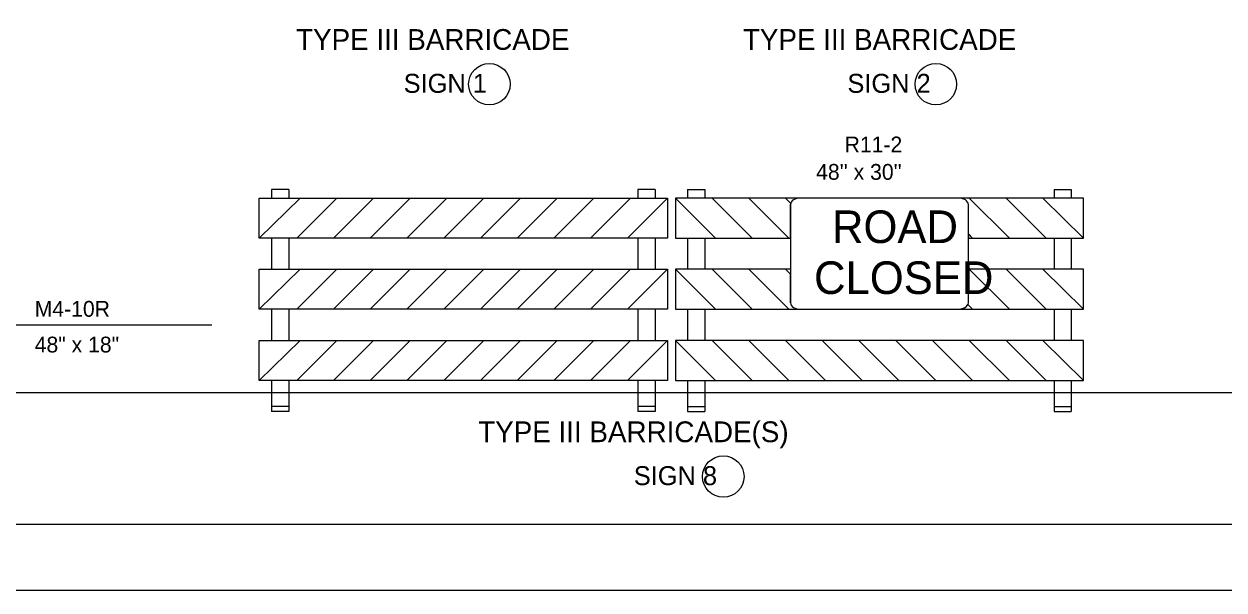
# Model space of a CAD drawing. Extents: x 1615234 to 1620694, y 898143 to 902846.
# Drawn here: x 1616745 to 1618110, y 899546 to 900191 of the extents above; entities that cross this region are included whole.
import ezdxf

# ---------------------------------------------------------------- set-up
doc = ezdxf.new("R2010")
doc.units = 0
for name, color, linetype in [('DEV BORDER CELL', 7, 'Continuous'), ('DEV TYPE 3 BARRICADE DOUBLE WITH R11-2 CELL', 7, 'Continuous'), ('DEV TYPE 3 BARRICADE WITH R11-2 M4-10R CELL', 7, 'Continuous'), ('DEV TYPE 3 BARRICADE WITH R11-3 M4-10L CELL', 7, 'Continuous'), ('DEV TYPE 3 BARRICADE WITH R11-4 M4-10R CELL', 7, 'Continuous'), ('Old_Level_28', 7, 'Continuous'), ('Scratch_Level_0', 7, 'Continuous'), ('Sheet Plot Border Outside CELL', 7, 'Continuous')]:
    doc.layers.add(name, color=color, linetype=linetype)

msp = doc.modelspace()

# ---------------------------------------------------------------- linework, layer by layer
at = {"layer": 'DEV BORDER CELL'}
msp.add_lwpolyline([(1620223.1, 902771.2), (1615723.1, 902771.2), (1615723.1, 899621.2), (1620223.1, 899621.2)], close=True, dxfattribs=at)
at = {"layer": 'DEV TYPE 3 BARRICADE DOUBLE WITH R11-2 CELL'}
for p, q in [((1617045.7, 900002.2), (1617026, 900002.2)), ((1617026, 900002.2), (1617026, 899992.4)), ((1617045.7, 900002.2), (1617045.7, 899992.4)), ((1617462.6, 900002.2), (1617442.9, 900002.2)), ((1617442.9, 900002.2), (1617442.9, 899992.4)), ((1617462.6, 900002.2), (1617462.6, 899992.4)), ((1617499.3, 900002.2), (1617519, 900002.2)), ((1617499.3, 900002.2), (1617499.3, 899992.4)), ((1617519, 900002.2), (1617519, 899992.4)), ((1617916.2, 900002.2), (1617935.9, 900002.2)), ((1617916.2, 900002.2), (1617916.2, 899992.4)), ((1617935.9, 900002.2), (1617935.9, 899992.4)), ((1617012.2, 899992.4), (1617476.4, 899992.4)), ((1617012.2, 899946.8), (1617012.2, 899992.4)), ((1617012.2, 899946.8), (1617012.2, 899992.4)), ((1617012.2, 899992.4), (1617058.5, 899992.4)), ((1617058.5, 899992.4), (1617012.2, 899946.8)), ((1617054.7, 899946.8), (1617100.3, 899992.4)), ((1617142, 899992.4), (1617096.5, 899946.8)), ((1617100.3, 899992.4), (1617142, 899992.4)), ((1617138.3, 899946.8), (1617183.8, 899992.4)), ((1617225.6, 899992.4), (1617180.1, 899946.8)), ((1617183.8, 899992.4), (1617225.6, 899992.4)), ((1617222, 899946.8), (1617267.5, 899992.4)), ((1617309.3, 899992.4), (1617263.8, 899946.8)), ((1617267.5, 899992.4), (1617309.3, 899992.4)), ((1617305.6, 899946.8), (1617351.1, 899992.4)), ((1617392.9, 899992.4), (1617347.3, 899946.8)), ((1617351.1, 899992.4), (1617392.9, 899992.4)), ((1617389.1, 899946.8), (1617434.6, 899992.4)), ((1617476.4, 899992.4), (1617430.9, 899946.8)), ((1617434.6, 899992.4), (1617476.4, 899992.4)), ((1617476.4, 899992.4), (1617476.4, 899946.8)), ((1617949.7, 899992.4), (1617485.5, 899992.4)), ((1617485.5, 899992.4), (1617485.5, 899946.8)), ((1617527.2, 899992.4), (1617485.5, 899992.4)), ((1617485.5, 899992.4), (1617531, 899946.8)), ((1617572.8, 899946.8), (1617527.2, 899992.4)), ((1617610.8, 899992.4), (1617569, 899992.4)), ((1617569, 899992.4), (1617614.5, 899946.8)), ((1617616.6, 899986.5), (1617610.8, 899992.4)), ((1617861.6, 899992.4), (1617819.8, 899992.4)), ((1617819.8, 899992.4), (1617865.4, 899946.8)), ((1617907.1, 899946.8), (1617861.6, 899992.4)), ((1617949.7, 899992.4), (1617903.4, 899992.4)), ((1617903.4, 899992.4), (1617949.7, 899946.8)), ((1617949.7, 899946.8), (1617949.7, 899992.4)), ((1617949.7, 899946.8), (1617949.7, 899992.4)), ((1617616.4, 899946.8), (1617616.4, 899985)), ((1617476.4, 899946.8), (1617012.2, 899946.8)), ((1617026, 899946.8), (1617026, 899911.4)), ((1617045.7, 899946.8), (1617045.7, 899911.4)), ((1617096.5, 899946.8), (1617054.7, 899946.8)), ((1617180.1, 899946.8), (1617138.3, 899946.8)), ((1617263.8, 899946.8), (1617222, 899946.8)), ((1617347.3, 899946.8), (1617305.6, 899946.8)), ((1617430.9, 899946.8), (1617389.1, 899946.8)), ((1617442.9, 899946.8), (1617442.9, 899911.4)), ((1617462.6, 899946.8), (1617462.6, 899911.4)), ((1617485.5, 899946.8), (1617616.4, 899946.8)), ((1617499.3, 899946.8), (1617499.3, 899911.4)), ((1617519, 899946.8), (1617519, 899911.4)), ((1617531, 899946.8), (1617572.8, 899946.8)), ((1617614.5, 899946.8), (1617616.4, 899946.8)), ((1617823.6, 899946.8), (1617818.8, 899951.7)), ((1617818.8, 899951.7), (1617818.8, 899946.8)), ((1617818.8, 899946.8), (1617823.6, 899946.8)), ((1617818.8, 899946.8), (1617949.7, 899946.8)), ((1617865.4, 899946.8), (1617907.1, 899946.8)), ((1617916.2, 899946.8), (1617916.2, 899911.4)), ((1617935.9, 899946.8), (1617935.9, 899911.4)), ((1617012.2, 899911.4), (1617476.4, 899911.4)), ((1617012.2, 899865.9), (1617012.2, 899911.4)), ((1617012.2, 899865.9), (1617012.2, 899911.4)), ((1617012.2, 899911.4), (1617058.5, 899911.4)), ((1617058.5, 899911.4), (1617012.2, 899865.9)), ((1617054.7, 899865.9), (1617100.3, 899911.4)), ((1617142, 899911.4), (1617096.5, 899865.9)), ((1617100.3, 899911.4), (1617142, 899911.4)), ((1617138.3, 899865.9), (1617183.8, 899911.4)), ((1617225.6, 899911.4), (1617180.1, 899865.9)), ((1617183.8, 899911.4), (1617225.6, 899911.4)), ((1617222, 899865.9), (1617267.5, 899911.4)), ((1617309.3, 899911.4), (1617263.8, 899865.9)), ((1617267.5, 899911.4), (1617309.3, 899911.4)), ((1617305.6, 899865.9), (1617351.1, 899911.4)), ((1617392.9, 899911.4), (1617347.3, 899865.9)), ((1617351.1, 899911.4), (1617392.9, 899911.4)), ((1617389.1, 899865.9), (1617434.6, 899911.4)), ((1617476.4, 899911.4), (1617430.9, 899865.9)), ((1617434.6, 899911.4), (1617476.4, 899911.4)), ((1617476.4, 899911.4), (1617476.4, 899865.9)), ((1617485.5, 899911.4), (1617485.5, 899865.9)), ((1617527.2, 899911.4), (1617485.5, 899911.4)), ((1617485.5, 899911.4), (1617531, 899865.9)), ((1617616.4, 899911.4), (1617485.5, 899911.4)), ((1617572.8, 899865.9), (1617527.2, 899911.4)), ((1617569, 899911.4), (1617614.5, 899865.9)), ((1617610.8, 899911.4), (1617569, 899911.4)), ((1617616.4, 899905.8), (1617610.8, 899911.4)), ((1617616.4, 899873.2), (1617616.4, 899905.8)), ((1617949.7, 899911.4), (1617818.8, 899911.4)), ((1617861.6, 899911.4), (1617819.8, 899911.4)), ((1617819.8, 899911.4), (1617865.4, 899865.9)), ((1617907.1, 899865.9), (1617861.6, 899911.4)), ((1617949.7, 899911.4), (1617903.4, 899911.4)), ((1617903.4, 899911.4), (1617949.7, 899865.9)), ((1617949.7, 899865.9), (1617949.7, 899911.4)), ((1617949.7, 899865.9), (1617949.7, 899911.4)), ((1617476.4, 899865.9), (1617012.2, 899865.9)), ((1617026, 899865.9), (1617026, 899830.4)), ((1617045.7, 899865.9), (1617045.7, 899830.4)), ((1617096.5, 899865.9), (1617054.7, 899865.9)), ((1617180.1, 899865.9), (1617138.3, 899865.9)), ((1617263.8, 899865.9), (1617222, 899865.9)), ((1617347.3, 899865.9), (1617305.6, 899865.9)), ((1617430.9, 899865.9), (1617389.1, 899865.9)), ((1617442.9, 899865.9), (1617442.9, 899830.4)), ((1617462.6, 899865.9), (1617462.6, 899830.4)), ((1617485.5, 899865.9), (1617949.7, 899865.9)), ((1617499.3, 899865.9), (1617499.3, 899830.4)), ((1617519, 899865.9), (1617519, 899830.4)), ((1617531, 899865.9), (1617572.8, 899865.9)), ((1617614.5, 899865.9), (1617628.1, 899865.9)), ((1617628.2, 899865.9), (1617807, 899865.9)), ((1617807, 899865.9), (1617823.6, 899865.9)), ((1617823.6, 899865.9), (1617818.3, 899871.2)), ((1617865.4, 899865.9), (1617907.1, 899865.9)), ((1617916.2, 899865.9), (1617916.2, 899830.4)), ((1617935.9, 899865.9), (1617935.9, 899830.4)), ((1617012.2, 899784.9), (1617012.2, 899830.4)), ((1617012.2, 899830.4), (1617058.5, 899830.4)), ((1617058.5, 899830.4), (1617012.2, 899784.9)), ((1617012.2, 899830.4), (1617476.4, 899830.4)), ((1617012.2, 899784.9), (1617012.2, 899830.4)), ((1617054.7, 899784.9), (1617100.3, 899830.4)), ((1617142, 899830.4), (1617096.5, 899784.9)), ((1617100.3, 899830.4), (1617142, 899830.4)), ((1617138.3, 899784.9), (1617183.8, 899830.4)), ((1617225.6, 899830.4), (1617180.1, 899784.9)), ((1617183.8, 899830.4), (1617225.6, 899830.4)), ((1617222, 899784.9), (1617267.5, 899830.4)), ((1617309.3, 899830.4), (1617263.8, 899784.9)), ((1617267.5, 899830.4), (1617309.3, 899830.4)), ((1617305.6, 899784.9), (1617351.1, 899830.4)), ((1617392.9, 899830.4), (1617347.3, 899784.9)), ((1617351.1, 899830.4), (1617392.9, 899830.4)), ((1617389.1, 899784.9), (1617434.6, 899830.4)), ((1617476.4, 899830.4), (1617430.9, 899784.9)), ((1617434.6, 899830.4), (1617476.4, 899830.4)), ((1617476.4, 899830.4), (1617476.4, 899784.9)), ((1617527.2, 899830.4), (1617485.5, 899830.4)), ((1617485.5, 899830.4), (1617531, 899784.9)), ((1617949.7, 899830.4), (1617485.5, 899830.4)), ((1617485.5, 899830.4), (1617485.5, 899784.9)), ((1617572.8, 899784.9), (1617527.2, 899830.4)), ((1617610.8, 899830.4), (1617569, 899830.4)), ((1617569, 899830.4), (1617614.5, 899784.9)), ((1617656.3, 899784.9), (1617610.8, 899830.4)), ((1617694.3, 899830.4), (1617652.6, 899830.4)), ((1617652.6, 899830.4), (1617698.1, 899784.9)), ((1617739.8, 899784.9), (1617694.3, 899830.4)), ((1617778.1, 899830.4), (1617736.3, 899830.4)), ((1617736.3, 899830.4), (1617781.8, 899784.9)), ((1617823.6, 899784.9), (1617778.1, 899830.4)), ((1617861.6, 899830.4), (1617819.8, 899830.4)), ((1617819.8, 899830.4), (1617865.4, 899784.9)), ((1617907.1, 899784.9), (1617861.6, 899830.4)), ((1617949.7, 899830.4), (1617903.4, 899830.4)), ((1617903.4, 899830.4), (1617949.7, 899784.9)), ((1617949.7, 899784.9), (1617949.7, 899830.4)), ((1617949.7, 899784.9), (1617949.7, 899830.4)), ((1617476.4, 899784.9), (1617012.2, 899784.9)), ((1617026, 899784.9), (1617026, 899749.4)), ((1617045.7, 899784.9), (1617045.7, 899749.4)), ((1617096.5, 899784.9), (1617054.7, 899784.9)), ((1617180.1, 899784.9), (1617138.3, 899784.9)), ((1617263.8, 899784.9), (1617222, 899784.9)), ((1617347.3, 899784.9), (1617305.6, 899784.9)), ((1617430.9, 899784.9), (1617389.1, 899784.9)), ((1617442.9, 899784.9), (1617442.9, 899749.4)), ((1617462.6, 899784.9), (1617462.6, 899749.4)), ((1617485.5, 899784.9), (1617949.7, 899784.9)), ((1617499.3, 899784.9), (1617499.3, 899749.4)), ((1617519, 899784.9), (1617519, 899749.4)), ((1617531, 899784.9), (1617572.8, 899784.9)), ((1617614.5, 899784.9), (1617656.3, 899784.9)), ((1617698.1, 899784.9), (1617739.8, 899784.9)), ((1617781.8, 899784.9), (1617823.6, 899784.9)), ((1617865.4, 899784.9), (1617907.1, 899784.9)), ((1617916.2, 899784.9), (1617916.2, 899749.4)), ((1617935.9, 899784.9), (1617935.9, 899749.4)), ((1617045.7, 899755.3), (1617026, 899755.3)), ((1617462.6, 899755.3), (1617442.9, 899755.3)), ((1617499.3, 899755.3), (1617519, 899755.3)), ((1617916.2, 899755.3), (1617935.9, 899755.3)), ((1617045.7, 899749.4), (1617026, 899749.4)), ((1617462.6, 899749.4), (1617442.9, 899749.4)), ((1617499.3, 899749.4), (1617519, 899749.4)), ((1617916.2, 899749.4), (1617935.9, 899749.4))]:
    msp.add_line(p, q, dxfattribs=at)
for points in [[(1617807, 899992.4), (1617628.2, 899992.4)], [(1617616.4, 899985), (1617616.4, 899873.2)], [(1617818.8, 899873.2), (1617818.8, 899985)]]:
    msp.add_lwpolyline(points, dxfattribs=at)
for centre, major_axis, start_param, end_param in [((1617628.2, 899985), (-11.8, 0), 4.712389, 6.283185), ((1617628.2, 899985), (-11.8, 0), 6.074789, 6.283185), ((1617807, 899985), (11.8, 0), 0, 1.571024), ((1617628.2, 899873.2), (11.8, 0), 3.141593, 4.712389), ((1617628.2, 899873.2), (-11.8, 0), 0, 1.570796), ((1617807, 899873.2), (11.8, 0), 4.712162, 6.283185), ((1617807, 899873.2), (11.8, 0), 4.712497, 5.996053)]:
    msp.add_ellipse(centre, major_axis=major_axis, ratio=0.625, start_param=start_param, end_param=end_param, dxfattribs=at)
at = {"layer": 'DEV TYPE 3 BARRICADE WITH R11-2 M4-10R CELL'}
msp.add_line((1616600.8, 899848.2), (1616958.3, 899848.2), dxfattribs=at)
at = {"layer": 'Old_Level_28'}
for centre in [(1617273.9, 900122), (1617781.8, 900122), (1617540, 899675.4)]:
    msp.add_circle(centre, 23.6, dxfattribs=at)
at = {"layer": 'Scratch_Level_0'}
msp.add_lwpolyline([(1620073.1, 902621.2), (1615873.1, 902621.2), (1615873.1, 899771.2), (1618509.6, 899771.2), (1618509.6, 900126), (1620073.1, 900126)], close=True, dxfattribs=at)
at = {"layer": 'Sheet Plot Border Outside CELL'}
msp.add_lwpolyline([(1615234.1, 899546.2), (1620298.1, 899546.2), (1620298.1, 902846.2), (1615234.1, 902846.2)], close=True, dxfattribs=at)

# ---------------------------------------------------------------- texts
at = {"layer": 'DEV TYPE 3 BARRICADE DOUBLE WITH R11-2 CELL'}
for s, height, p in [('R11-2', 18, (1617678, 900044.4)), ("48'' x 30''", 18, (1617645.6, 900013.2)), ('ROAD', 37.11, (1617663.6, 899941.2)), ('CLOSED', 37.11, (1617643.2, 899883.2)), ('TYPE III BARRICADE(S)', 23.645, (1617261.2, 899714.5))]:
    msp.add_text(s, height=height, rotation=360, dxfattribs=at).set_placement(p)
at = {"layer": 'DEV TYPE 3 BARRICADE WITH R11-2 M4-10R CELL'}
for s, p in [('M4-10R', (1616756.7, 899857.3)), ('48" x 18"', (1616756.7, 899816.6))]:
    msp.add_text(s, height=18, dxfattribs=at).set_placement(p)
at = {"layer": 'DEV TYPE 3 BARRICADE WITH R11-3 M4-10L CELL'}
msp.add_text('TYPE III BARRICADE', height=23.645, dxfattribs=at).set_placement((1617562.3, 900161.1))
at = {"layer": 'DEV TYPE 3 BARRICADE WITH R11-4 M4-10R CELL'}
msp.add_text('TYPE III BARRICADE', height=23.645, rotation=360, dxfattribs=at).set_placement((1617054, 900161.1))
at = {"layer": 'Old_Level_28'}
for s, p in [('SIGN 1', (1617176.4, 900112.2)), ('SIGN 2', (1617681.2, 900112.2)), ('SIGN 8', (1617438.2, 899665.6))]:
    msp.add_text(s, height=21.6, dxfattribs=at).set_placement(p)

doc.saveas('drawing.dxf')
